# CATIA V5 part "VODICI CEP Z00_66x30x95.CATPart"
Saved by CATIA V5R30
Part number: VODICI CEP Z00/66x30x95
Bounding box of the stored display mesh (mm): x -9 to 161, y -23.5 to 23.5, z -23.5 to 23.5
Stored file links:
  C:\Users\ondra\Desktop\PŘÍLOHA P III\CATIA\VODICI CEP Z00_66x30x95.CATPart
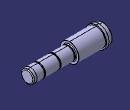
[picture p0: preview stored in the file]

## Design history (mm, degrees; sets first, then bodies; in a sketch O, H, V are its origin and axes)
Set1
  DatumSurface1 to DatumSurface45 "Z00/66x3"
  Join1: Elements (DatumSurface1; DatumSurface2; DatumSurface3; DatumSurface4; DatumSurface5; DatumSurface6; DatumSurface7; DatumSurface8; DatumSurface9; DatumSurface10; DatumSurface11; DatumSurface12; DatumSurface13; DatumSurface14; DatumSurface15; DatumSurface16; DatumSurface17; DatumSurface18; DatumSurface19; DatumSurface20; DatumSurface21; DatumSurface22; DatumSurface23; DatumSurface24; DatumSurface25; DatumSurface26; DatumSurface27; DatumSurface28; DatumSurface29; DatumSurface30; DatumSurface31; DatumSurface32; DatumSurface33; DatumSurface34; DatumSurface35; DatumSurface36; DatumSurface37; DatumSurface38; DatumSurface39; DatumSurface40; DatumSurface41; DatumSurface42; DatumSurface43; DatumSurface44; DatumSurface45)
Body1 (main body)
  CloseSurface1: CloseElement Join1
